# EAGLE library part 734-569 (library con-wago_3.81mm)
Serie 734, Federleiste mit abgewinkelten Einlötstiften / Series 734, Female connector with angled solder pins Polzahl / Pole No.: 9 Bemessungsspannung / Rated Voltage: 160 V Nennstrom / Nominal Current: 10 A Lötstiftlänge: / Solder Pin Length: 3.8 mm Farbe / Color: orange / orange Stand: 01.01.2012. Die jeweils aktuellen Daten zu diesem Artikel finden Sie in unserem Produktkatalog, den Sie unter www.wago.com einsehen können. As of: 01/01/2012. Please find the newest data for this article in our product catalogue, which can be viewed under www.wago.com.
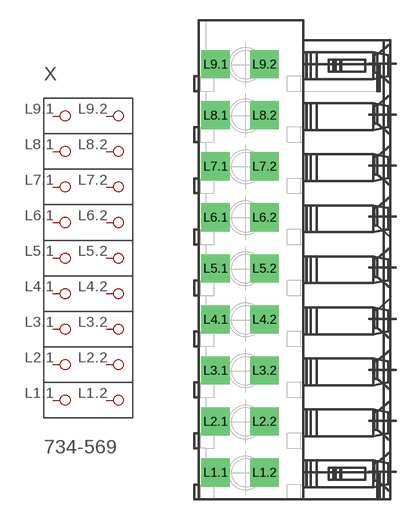
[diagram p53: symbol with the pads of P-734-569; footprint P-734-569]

Designator prefix X

## 734-569  [P-734-569]
L1.1  P1.1
L1.2  P1.2
L2.1  P2.1
L2.2  P2.2
L3.1  P3.1
L3.2  P3.2
L4.1  P4.1
L4.2  P4.2
L5.1  P5.1
L5.2  P5.2
L6.1  P6.1
L6.2  P6.2
L7.1  P7.1
L7.2  P7.2
L8.1  P8.1
L8.2  P8.2
L9.1  P9.1
L9.2  P9.2

## Footprint P-734-569 (pad centres in mm)
drill 1.4 square: L1.1 -5.926,-15.885; L1.2 -2.276,-15.885; L2.1 -5.926,-12.075; L2.2 -2.276,-12.075; L3.1 -5.926,-8.265; L3.2 -2.276,-8.265; L4.1 -5.926,-4.455; L4.2 -2.276,-4.455; L5.1 -5.926,-0.645; L5.2 -2.276,-0.645; L6.1 -5.926,3.165; L6.2 -2.276,3.165; L7.1 -5.926,6.975; L7.2 -2.276,6.975; L8.1 -5.926,10.785; L8.2 -2.276,10.785; L9.1 -5.926,14.595; L9.2 -2.276,14.595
